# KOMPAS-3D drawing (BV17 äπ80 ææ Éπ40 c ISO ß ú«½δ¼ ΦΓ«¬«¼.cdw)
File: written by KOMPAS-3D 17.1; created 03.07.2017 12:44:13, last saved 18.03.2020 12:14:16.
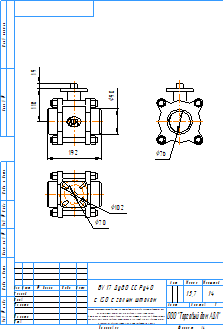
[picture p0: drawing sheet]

Sheet 1: A4, portrait

Title block, sheet 1: name: BV17 Ду80 СС Ру40 / c ISO с голым штоком; material: Сталь 20  ГОСТ 1050-88; mass: 15,7; sheets: 1; sheet format: A4; stored path: C:\Users\kka\KOMPAS_Work\!Trash\СС02 СС03 ФФ Смотровые стекла\СС01.cdw

Views: Спереди 4, Проекционный вид 5, Проекционный вид 6
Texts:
  Klimkovich
  ADL
  Рама для чертежей
  Лит-Масса-Масштаб
  Материал-Предприятие
  Масштаб
  Изм.
  Лист
  № докум.
  Подп.
  Дата
  Лит.
  Разраб.
  Пров.
  Т.контр.
  Листов
  Внимание! Данный продукт является объектом авторского права ООО «Торговый Дом АДЛ».
  Запрещается изменение, копирование, распространение
  (в том числе путем копирования на другие сайты и ресурсы в Интернете)
  или любое иное использование информации и объектов без предварительного
  согласия правообладателя (ООО «Торговый Дом АДЛ»).
  Н.контр.
  Утв.
  ООО "Торговый дом АДЛ"
  Изменение
  Номер документа
  Подпись
  Обозначение документа
  Наименование изделия
  Масса изделия по ГОСТ 2.109-73
  Порядковый номер листа
  Общее количество листов в документе
  Характер работы, выполненной лицом, подписавшим документ
  Наименование или индекс предприятия, выпускающего документ
  Инв. № подл.
  Подп. и дата
  Взам. инв. №
  Инв. № дубл.
  Инвентарный номер подлинника по ГОСТ 2.501-68
  Подпись принявшего подлинник в отдел технической документации
  Инвентарный номер подлинника, взамен которого выпущен данный подлинник
  Инвентарный номер дубликата по ГОСТ 2.502-68
  Подпись принявшего дубликат в отдел технической документации
  Справ. №
  Перв. примен.
  Обозначение документа, взамен или на основании которого выпущен данный документ
  Обозначение документа, в котором впервые записан данный документ
  Подпись лица, копировавшего чертеж
  Обозначение формата листа
  !Рама для чертежа
Dimensions and other numbers on the sheet: 192; 118; 90; 19; 102; 70; 76; 1:4; 1; 15,7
